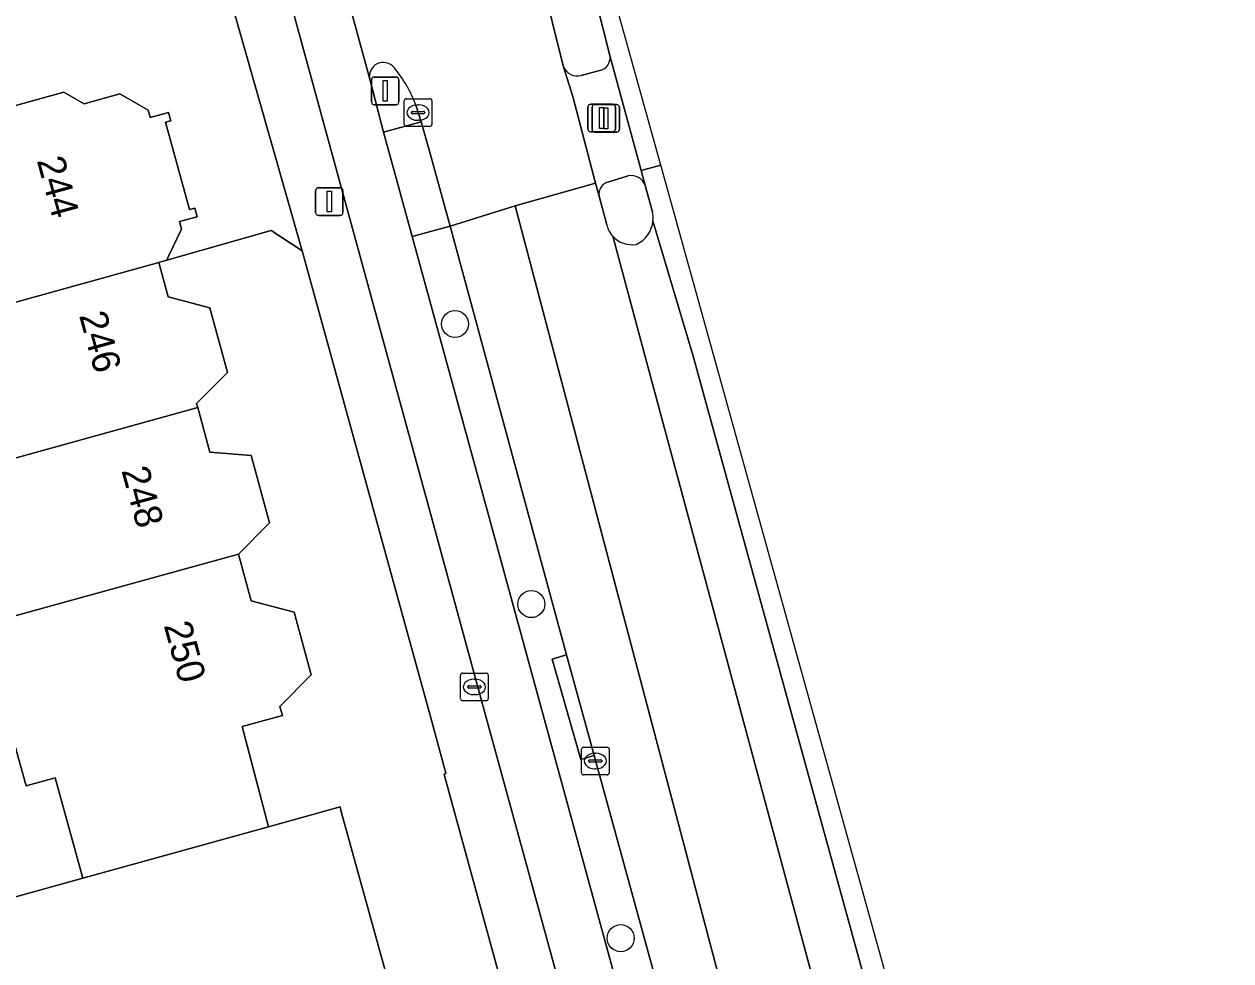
# Model space of a CAD drawing. Extents: x 162250 to 162661, y 380743 to 381606.
# Drawn here: x 162522.36 to 162566, y 381174.18 to 381208.05 of the extents above; entities that cross this region are included whole.
import ezdxf

# ---------------------------------------------------------------- set-up
doc = ezdxf.new("R2010")
doc.units = 0
for name, color, linetype in [('IMGEO_Berm_open', 7, 'Continuous'), ('IMGEO_Boom', 7, 'Continuous'), ('IMGEO_Brandkraan', 7, 'Continuous'), ('IMGEO_Erf', 7, 'Continuous'), ('IMGEO_Fietspad_gesloten', 7, 'Continuous'), ('IMGEO_Kolk', 7, 'Continuous'), ('IMGEO_Lichtmast', 7, 'Continuous'), ('IMGEO_Pand', 7, 'Continuous'), ('IMGEO_Pand_nummerreeks', 7, 'Continuous'), ('IMGEO_Rijbaan_regionaal_gesloten', 7, 'Continuous'), ('IMGEO_Verkeerseiland_open', 7, 'Continuous'), ('IMGEO_Verkeersregelinstallatiepaal', 7, 'Continuous'), ('IMGEO_Voetpad_gesloten', 7, 'Continuous'), ('IMGEO_Voetpad_open', 7, 'Continuous')]:
    doc.layers.add(name, color=color, linetype=linetype)

msp = doc.modelspace()

# ---------------------------------------------------------------- linework, layer by layer
at = {"layer": 'IMGEO_Berm_open'}
msp.add_lwpolyline([(162553.008, 381145.025), (162552.925, 381145.33), (162550.374, 381154.672), (162550.34, 381154.796), (162542.98, 381181.61), (162542.491, 381181.463), (162541.461, 381185.086), (162541.982, 381185.24), (162537.767, 381200.743), (162536.398, 381200.372), (162539.144, 381190.342), (162540.943, 381183.77), (162548.984, 381154.395), (162551.592, 381144.84), (162551.645, 381144.647), (162554.806, 381133.124), (162560.736, 381111.446), (162562.992, 381103.198), (162573.052, 381066.398), (162577.335, 381050.801)], dxfattribs=at)
at = {"layer": 'IMGEO_Boom'}
for centre in [(162537.943, 381197.208), (162540.706, 381187.08), (162543.938, 381175.003)]:
    msp.add_circle(centre, 0.489, dxfattribs=at)
at = {"layer": 'IMGEO_Brandkraan'}
for p, q in [((162538.145, 381183.661), (162538.145, 381184.513)), ((162538.22, 381184.587), (162539.072, 381184.587)), ((162539.146, 381184.513), (162539.146, 381183.661)), ((162538.404, 381184.081), (162538.404, 381184.093)), ((162538.447, 381184.13), (162538.845, 381184.13)), ((162538.633, 381184.367), (162538.658, 381184.367)), ((162538.888, 381184.093), (162538.888, 381184.081)), ((162538.842, 381184.044), (162538.444, 381184.044)), ((162538.656, 381183.807), (162538.631, 381183.807)), ((162539.072, 381183.587), (162538.22, 381183.587))]:
    msp.add_line(p, q, dxfattribs=at)
for points in [[(162538.145, 381183.661), (162538.145, 381184.513)], [(162538.22, 381184.587), (162539.072, 381184.587)], [(162539.146, 381184.513), (162539.146, 381183.661)], [(162539.072, 381183.587), (162538.22, 381183.587)]]:
    msp.add_lwpolyline(points, dxfattribs=at)
for centre, radius, start, end in [((162538.222, 381184.511), 0.0765, 91.552, 178.448), ((162538.222, 381184.511), 0.0765, 91.552, 178.448), ((162539.07, 381184.511), 0.0765, 1.552, 88.448), ((162539.07, 381184.511), 0.0765, 1.552, 88.448), ((162538.444, 381184.09), 0.0403, 85.8775, 175.7526), ((162538.441, 381184.08), 0.0366, 178.938, 274.7102), ((162538.845, 381184.087), 0.043, 264.8664, 352.4533), ((162538.849, 381184.092), 0.0386, 1.7309, 96.639), ((162538.222, 381183.663), 0.0765, 181.552, 268.448), ((162538.222, 381183.663), 0.0765, 181.552, 268.448), ((162539.07, 381183.663), 0.0765, 271.552, 358.448), ((162539.07, 381183.663), 0.0765, 271.552, 358.448)]:
    msp.add_arc(centre, radius, start, end, dxfattribs=at)
for centre, major_axis, ratio, start_param, end_param in [((162538.632, 381184.087), (-0.387, 0.002), 0.722429, 4.712389, 7.853982), ((162538.657, 381184.087), (-0.39, 0.002), 0.717154, 1.570796, 4.712389)]:
    msp.add_ellipse(centre, major_axis=major_axis, ratio=ratio, start_param=start_param, end_param=end_param, dxfattribs=at)
at = {"layer": 'IMGEO_Erf'}
for points in [[(162545.286, 381152.678), (162537.55, 381180.925), (162537.616, 381180.963), (162537.065, 381182.965), (162532.417, 381199.851), (162531.293, 381200.584), (162527.522, 381199.515), (162527.229, 381199.434), (162527.572, 381198.183), (162529.078, 381197.789), (162529.717, 381195.458), (162528.601, 381194.329), (162528.64, 381194.185), (162529.082, 381192.577), (162530.57, 381192.447), (162531.235, 381190.019), (162530.114, 381188.885), (162530.577, 381187.195), (162532.125, 381186.79), (162532.748, 381184.52), (162531.613, 381183.372), (162531.701, 381183.051), (162530.245, 381182.652), (162531.203, 381179.03), (162533.786, 381179.745), (162533.844, 381179.534), (162540.468, 381155.608)], [(162517.179, 381175.147), (162524.487, 381177.17), (162523.483, 381180.798), (162522.431, 381180.51), (162521.694, 381183.198)]]:
    msp.add_lwpolyline(points, dxfattribs=at)
at = {"layer": 'IMGEO_Fietspad_gesloten'}
for points in [[(162508.721, 381294.058), (162520.721, 381250), (162524.95, 381234.475), (162526.439, 381228.987), (162532.158, 381208.274), (162537.019, 381190.487), (162538.98, 381183.33), (162547.107, 381153.663), (162547.143, 381153.533), (162549.695, 381144.216), (162549.852, 381143.643), (162552.836, 381132.744), (162558.72, 381111.249), (162561.27, 381101.934), (162571.085, 381066.091), (162575.392, 381050.363), (162582.804, 381023.355), (162585.413, 381013.87), (162586.64, 381009.407), (162588.336, 381003.241), (162600.985, 380956.955), (162611.456, 380918.623), (162619.54, 380889.111), (162626.231, 380864.638)], [(162611.747, 380924.889), (162608.338, 380937.386), (162606.977, 380942.372), (162603.154, 380956.316), (162590.219, 381003.716), (162588.433, 381010.254), (162587.309, 381014.367), (162584.526, 381024.553), (162577.335, 381050.801), (162573.052, 381066.398), (162562.992, 381103.198), (162560.736, 381111.446), (162554.806, 381133.124), (162551.645, 381144.647), (162551.592, 381144.84), (162548.984, 381154.395), (162540.943, 381183.77), (162539.144, 381190.342), (162536.398, 381200.372), (162535.609, 381203.223), (162535.353, 381204.147), (162534.863, 381206.056), (162528.007, 381231.163)]]:
    msp.add_lwpolyline(points, dxfattribs=at)
at = {"layer": 'IMGEO_Kolk'}
for p, q in [((162536.108, 381204.425), (162536.108, 381205.277)), ((162536.183, 381205.351), (162537.035, 381205.351)), ((162536.596, 381205.131), (162536.621, 381205.131)), ((162537.109, 381205.277), (162537.109, 381204.425)), ((162536.367, 381204.845), (162536.367, 381204.857)), ((162536.805, 381204.808), (162536.407, 381204.808)), ((162536.41, 381204.894), (162536.808, 381204.894)), ((162536.851, 381204.857), (162536.851, 381204.845)), ((162537.035, 381204.351), (162536.183, 381204.351)), ((162536.619, 381204.571), (162536.594, 381204.571)), ((162542.594, 381181.905), (162543.446, 381181.905)), ((162542.519, 381180.979), (162542.519, 381181.831)), ((162543.007, 381181.685), (162543.032, 381181.685)), ((162543.52, 381181.831), (162543.52, 381180.979)), ((162542.778, 381181.399), (162542.778, 381181.411)), ((162543.216, 381181.362), (162542.818, 381181.362)), ((162542.821, 381181.448), (162543.219, 381181.448)), ((162543.03, 381181.125), (162543.005, 381181.125)), ((162543.262, 381181.411), (162543.262, 381181.399)), ((162543.446, 381180.905), (162542.594, 381180.905))]:
    msp.add_line(p, q, dxfattribs=at)
for points in [[(162536.108, 381204.425), (162536.108, 381205.277)], [(162536.183, 381205.351), (162537.035, 381205.351)], [(162537.109, 381205.277), (162537.109, 381204.425)], [(162537.035, 381204.351), (162536.183, 381204.351)], [(162542.594, 381181.905), (162543.446, 381181.905)], [(162542.519, 381180.979), (162542.519, 381181.831)], [(162543.52, 381181.831), (162543.52, 381180.979)], [(162543.446, 381180.905), (162542.594, 381180.905)]]:
    msp.add_lwpolyline(points, dxfattribs=at)
for centre, radius, start, end in [((162536.185, 381205.275), 0.0765, 91.552, 178.448), ((162536.185, 381205.275), 0.0765, 91.552, 178.448), ((162537.033, 381205.275), 0.0765, 1.552, 88.448), ((162537.033, 381205.275), 0.0765, 1.552, 88.448), ((162536.407, 381204.854), 0.0403, 85.8775, 175.7526), ((162536.404, 381204.844), 0.0366, 178.938, 274.7102), ((162536.808, 381204.851), 0.043, 264.8664, 352.4533), ((162536.812, 381204.856), 0.0386, 1.7309, 96.639), ((162536.185, 381204.427), 0.0765, 181.552, 268.448), ((162536.185, 381204.427), 0.0765, 181.552, 268.448), ((162537.033, 381204.427), 0.0765, 271.552, 358.448), ((162537.033, 381204.427), 0.0765, 271.552, 358.448), ((162542.596, 381181.829), 0.0765, 91.552, 178.448), ((162542.596, 381181.829), 0.0765, 91.552, 178.448), ((162543.444, 381181.829), 0.0765, 1.552, 88.448), ((162543.444, 381181.829), 0.0765, 1.552, 88.448), ((162542.818, 381181.408), 0.0403, 85.8775, 175.7526), ((162542.815, 381181.398), 0.0366, 178.938, 274.7102), ((162543.219, 381181.405), 0.043, 264.8664, 352.4533), ((162543.223, 381181.41), 0.0386, 1.7309, 96.639), ((162542.596, 381180.981), 0.0765, 181.552, 268.448), ((162542.596, 381180.981), 0.0765, 181.552, 268.448), ((162543.444, 381180.981), 0.0765, 271.552, 358.448), ((162543.444, 381180.981), 0.0765, 271.552, 358.448)]:
    msp.add_arc(centre, radius, start, end, dxfattribs=at)
for centre, major_axis, ratio, start_param, end_param in [((162536.595, 381204.851), (-0.387, 0.002), 0.722429, 4.712389, 7.853982), ((162536.62, 381204.851), (-0.39, 0.002), 0.717154, 1.570796, 4.712389), ((162543.006, 381181.405), (-0.387, 0.002), 0.722429, 4.712389, 7.853982), ((162543.031, 381181.405), (-0.39, 0.002), 0.717154, 1.570796, 4.712389)]:
    msp.add_ellipse(centre, major_axis=major_axis, ratio=ratio, start_param=start_param, end_param=end_param, dxfattribs=at)
at = {"layer": 'IMGEO_Lichtmast'}
for p, q in [((162542.902, 381204.241), (162542.902, 381205.041)), ((162542.902, 381205.041), (162542.902, 381204.241)), ((162543.002, 381205.141), (162543.792, 381205.141)), ((162543.792, 381205.141), (162543.002, 381205.141)), ((162543.892, 381205.041), (162543.892, 381204.241)), ((162543.892, 381204.241), (162543.892, 381205.041)), ((162543.792, 381204.141), (162543.002, 381204.141)), ((162543.002, 381204.141), (162543.792, 381204.141))]:
    msp.add_line(p, q, dxfattribs=at)
msp.add_lwpolyline([(162543.322, 381205.016), (162543.472, 381205.016), (162543.472, 381204.266), (162543.322, 381204.266), (162543.322, 381205.016)], dxfattribs=at)
for centre, start, end in [((162543.002, 381205.041), 90, 180), ((162543.002, 381205.041), 90, 180), ((162543.792, 381205.041), 0, 90), ((162543.792, 381205.041), 360, 90), ((162543.002, 381204.241), 180, 270), ((162543.002, 381204.241), 180, 270), ((162543.792, 381204.241), 270, 0), ((162543.792, 381204.241), 270, 0)]:
    msp.add_arc(centre, 0.1, start, end, dxfattribs=at)
at = {"layer": 'IMGEO_Pand'}
msp.add_lwpolyline([(162516.659, 381196.507), (162527.229, 381199.434), (162527.522, 381199.515), (162527.599, 381199.678), (162528.053, 381200.637), (162527.979, 381200.908), (162528.62, 381201.084), (162528.535, 381201.394), (162528.345, 381201.342), (162527.48, 381204.498), (162527.67, 381204.55), (162527.587, 381204.851), (162526.922, 381204.668), (162526.848, 381204.936), (162525.818, 381205.523), (162524.534, 381205.171), (162523.801, 381205.589), (162520.567, 381204.702)], dxfattribs=at)
for points in [[(162528.64, 381194.185), (162528.601, 381194.329), (162529.717, 381195.458), (162529.078, 381197.789), (162527.572, 381198.183), (162527.229, 381199.434), (162516.659, 381196.507), (162517.358, 381193.957), (162518.539, 381194.281), (162519.226, 381191.778), (162518.061, 381191.459), (162518.113, 381191.271)], [(162528.64, 381194.185), (162518.113, 381191.271), (162518.908, 381188.369), (162520.056, 381188.684), (162520.712, 381186.292), (162530.114, 381188.885), (162531.235, 381190.019), (162530.57, 381192.447), (162529.082, 381192.577)], [(162520.712, 381186.292), (162519.589, 381185.985), (162520.446, 381182.856), (162521.694, 381183.198), (162522.431, 381180.51), (162523.483, 381180.798), (162524.487, 381177.17), (162531.203, 381179.03), (162530.245, 381182.652), (162531.701, 381183.051), (162531.613, 381183.372), (162532.748, 381184.52), (162532.125, 381186.79), (162530.577, 381187.195), (162530.114, 381188.885)], [(162524.487, 381177.17), (162517.179, 381175.147), (162516.879, 381176.23), (162511.537, 381174.751), (162515.452, 381155.029), (162516.426, 381150.124), (162516.634, 381150.165), (162523.606, 381151.549), (162523.763, 381150.983), (162532.204, 381153.32), (162540.468, 381155.608), (162533.844, 381179.534), (162533.786, 381179.745), (162531.203, 381179.03)]]:
    msp.add_lwpolyline(points, close=True, dxfattribs=at)
at = {"layer": 'IMGEO_Rijbaan_regionaal_gesloten'}
for points in [[(162545.39, 381202.947), (162541.62, 381216.506), (162529.09, 381267.097), (162526.533, 381277.419), (162506.293, 381346.192), (162501.803, 381357.869), (162495.049, 381375.437), (162487.336, 381390.854), (162486.734, 381390.552), (162488.723, 381386.618), (162489.098, 381385.884)], [(162528.007, 381231.163), (162534.863, 381206.056)], [(162543.035, 381208.92), (162543.558, 381206.865), (162544.673, 381202.753), (162545.39, 381202.947)], [(162536.536, 381205.084), (162536.726, 381204.513), (162537.019, 381203.451), (162537.767, 381200.743), (162540.124, 381201.475), (162543.029, 381202.295), (162542.209, 381205.429), (162541.867, 381206.505), (162541.523, 381207.891), (162541.384, 381208.45)], [(162604.23, 380992.009), (162599.016, 381010.476), (162591.435, 381037.32), (162559.589, 381151.874), (162545.39, 381202.947), (162544.673, 381202.753), (162544.818, 381202.219), (162545.081, 381201.258)], [(162543.432, 381200.793), (162543.152, 381201.827), (162543.029, 381202.295), (162540.124, 381201.475), (162556.025, 381141.32), (162556.267, 381140.725), (162561.982, 381119.806), (162563.768, 381113.225), (162565.639, 381106.468), (162577.173, 381064.266), (162584.449, 381036.623), (162587.606, 381025.501), (162590.528, 381015.212), (162591.173, 381012.938), (162595.042, 380999.313), (162597.541, 380990.23), (162600.546, 380991.029), (162599.675, 380994.301)], [(162540.124, 381201.475), (162537.767, 381200.743), (162541.982, 381185.24), (162542.98, 381181.61), (162550.34, 381154.796), (162550.374, 381154.672), (162552.925, 381145.33), (162553.008, 381145.025)], [(162555.673, 381142.187), (162556.025, 381141.32), (162540.124, 381201.475)], [(162569.845, 381112.873), (162562.469, 381138.221), (162546.555, 381196.038), (162545.104, 381200.933)], [(162545.104, 381200.933), (162546.555, 381196.038), (162562.469, 381138.221), (162569.845, 381112.873)], [(162543.648, 381200.38), (162544.792, 381196.117), (162567.409, 381112.237)], [(162567.409, 381112.237), (162544.792, 381196.117), (162543.648, 381200.38)]]:
    msp.add_lwpolyline(points, dxfattribs=at)
for centre, radius, start, end in [((162535.35, 381206.164), 0.499, 38.7418, 192.4891), ((162532.527, 381203.713), 4.237, 18.8833, 40.704), ((162544.046, 381201.021), 1.062, 355.2201, 12.8759), ((162544.348, 381201.009), 0.942, 193.2792, 221.9401), ((162544.08, 381201.024), 1.028, 294.0476, 354.941), ((162544.343, 381201.01), 0.938, 222.2051, 279.557)]:
    msp.add_arc(centre, radius, start, end, dxfattribs=at)
at = {"layer": 'IMGEO_Verkeerseiland_open'}
for points in [[(162543.558, 381206.865), (162543.035, 381208.92)], [(162541.384, 381208.45), (162541.523, 381207.891), (162541.867, 381206.505)], [(162542.509, 381206.19), (162543.219, 381206.38)], [(162534.863, 381206.056), (162535.353, 381204.147), (162536.726, 381204.513), (162536.536, 381205.084)], [(162544.21, 381202.56), (162543.475, 381202.337)], [(162545.081, 381201.258), (162544.818, 381202.219)], [(162543.152, 381201.827), (162543.432, 381200.793)]]:
    msp.add_lwpolyline(points, dxfattribs=at)
for centre, radius, start, end in [((162543.067, 381206.847), 0.491, 287.9873, 2.108), ((162535.35, 381206.164), 0.499, 38.7418, 192.4891), ((162532.527, 381203.713), 4.237, 18.8833, 40.704), ((162542.372, 381206.723), 0.55, 203.3585, 284.3714), ((162544.322, 381202.048), 0.525, 19.0758, 102.352), ((162543.598, 381201.902), 0.452, 105.7592, 189.5459), ((162544.046, 381201.021), 1.062, 355.2201, 12.8759), ((162544.348, 381201.009), 0.942, 193.2792, 221.9401), ((162544.08, 381201.024), 1.028, 294.0476, 354.941), ((162544.343, 381201.01), 0.938, 222.2051, 279.557)]:
    msp.add_arc(centre, radius, start, end, dxfattribs=at)
at = {"layer": 'IMGEO_Verkeersregelinstallatiepaal'}
for p, q in [((162534.924, 381205.235), (162534.924, 381206.035)), ((162534.924, 381206.035), (162534.924, 381205.235)), ((162535.024, 381206.135), (162535.814, 381206.135)), ((162535.814, 381206.135), (162535.024, 381206.135)), ((162535.914, 381206.035), (162535.914, 381205.235)), ((162535.914, 381205.235), (162535.914, 381206.035)), ((162535.814, 381205.135), (162535.024, 381205.135)), ((162535.024, 381205.135), (162535.814, 381205.135)), ((162542.754, 381204.255), (162542.754, 381205.055)), ((162542.754, 381205.055), (162542.754, 381204.255)), ((162542.854, 381205.155), (162543.644, 381205.155)), ((162543.644, 381205.155), (162542.854, 381205.155)), ((162543.744, 381205.055), (162543.744, 381204.255)), ((162543.744, 381204.255), (162543.744, 381205.055)), ((162543.644, 381204.155), (162542.854, 381204.155)), ((162542.854, 381204.155), (162543.644, 381204.155)), ((162532.904, 381201.232), (162532.904, 381202.032)), ((162532.904, 381202.032), (162532.904, 381201.232)), ((162533.004, 381202.132), (162533.794, 381202.132)), ((162533.794, 381202.132), (162533.004, 381202.132)), ((162533.894, 381202.032), (162533.894, 381201.232)), ((162533.894, 381201.232), (162533.894, 381202.032)), ((162533.794, 381201.132), (162533.004, 381201.132)), ((162533.004, 381201.132), (162533.794, 381201.132))]:
    msp.add_line(p, q, dxfattribs=at)
for points in [[(162535.344, 381206.01), (162535.494, 381206.01), (162535.494, 381205.26), (162535.344, 381205.26), (162535.344, 381206.01)], [(162543.174, 381205.03), (162543.324, 381205.03), (162543.324, 381204.28), (162543.174, 381204.28), (162543.174, 381205.03)], [(162533.324, 381202.007), (162533.474, 381202.007), (162533.474, 381201.257), (162533.324, 381201.257), (162533.324, 381202.007)]]:
    msp.add_lwpolyline(points, dxfattribs=at)
for centre, start, end in [((162535.024, 381206.035), 90, 180), ((162535.024, 381206.035), 90, 180), ((162535.814, 381206.035), 0, 90), ((162535.814, 381206.035), 360, 90), ((162535.024, 381205.235), 180, 270), ((162535.024, 381205.235), 180, 270), ((162535.814, 381205.235), 270, 0), ((162535.814, 381205.235), 270, 0), ((162542.854, 381205.055), 90, 180), ((162542.854, 381205.055), 90, 180), ((162543.644, 381205.055), 0, 90), ((162543.644, 381205.055), 360, 90), ((162542.854, 381204.255), 180, 270), ((162542.854, 381204.255), 180, 270), ((162543.644, 381204.255), 270, 0), ((162543.644, 381204.255), 270, 0), ((162533.004, 381202.032), 90, 180), ((162533.004, 381202.032), 90, 180), ((162533.794, 381202.032), 0, 90), ((162533.794, 381202.032), 360, 90), ((162533.004, 381201.232), 180, 270), ((162533.004, 381201.232), 180, 270), ((162533.794, 381201.232), 270, 0), ((162533.794, 381201.232), 270, 0)]:
    msp.add_arc(centre, 0.1, start, end, dxfattribs=at)
at = {"layer": 'IMGEO_Voetpad_gesloten'}
for points in [[(162544.818, 381202.219), (162544.673, 381202.753), (162543.558, 381206.865)], [(162541.867, 381206.505), (162542.209, 381205.429), (162543.029, 381202.295), (162543.152, 381201.827)], [(162543.219, 381206.38), (162542.509, 381206.19)], [(162543.475, 381202.337), (162544.21, 381202.56)]]:
    msp.add_lwpolyline(points, dxfattribs=at)
for centre, radius, start, end in [((162543.067, 381206.847), 0.491, 287.9873, 2.108), ((162542.372, 381206.723), 0.55, 203.3585, 284.3714), ((162544.322, 381202.048), 0.525, 19.0758, 102.352), ((162543.598, 381201.902), 0.452, 105.7592, 189.5459)]:
    msp.add_arc(centre, radius, start, end, dxfattribs=at)
at = {"layer": 'IMGEO_Voetpad_open'}
for points in [[(162520.567, 381204.702), (162523.801, 381205.589), (162524.534, 381205.171), (162525.818, 381205.523), (162526.848, 381204.936), (162526.922, 381204.668), (162527.587, 381204.851), (162527.67, 381204.55), (162527.48, 381204.498), (162528.345, 381201.342), (162528.535, 381201.394), (162528.62, 381201.084), (162527.979, 381200.908), (162528.053, 381200.637), (162527.599, 381199.678), (162527.522, 381199.515), (162531.293, 381200.584), (162532.417, 381199.851), (162530.224, 381207.557), (162529.072, 381211.608)], [(162529.072, 381211.608), (162530.224, 381207.557), (162532.417, 381199.851), (162537.065, 381182.965), (162537.616, 381180.963), (162537.55, 381180.925), (162545.286, 381152.678), (162547.143, 381153.533), (162547.107, 381153.663), (162538.98, 381183.33), (162537.019, 381190.487), (162532.158, 381208.274)]]:
    msp.add_lwpolyline(points, dxfattribs=at)
for points in [[(162536.398, 381200.372), (162537.767, 381200.743), (162537.019, 381203.451), (162536.726, 381204.513), (162535.353, 381204.147), (162535.609, 381203.223)], [(162541.982, 381185.24), (162541.461, 381185.086), (162542.491, 381181.463), (162542.98, 381181.61)]]:
    msp.add_lwpolyline(points, close=True, dxfattribs=at)

# ---------------------------------------------------------------- texts
at = {"layer": 'IMGEO_Pand_nummerreeks'}
for s, p in [('244', (162522.816, 381203.121)), ('246', (162524.346, 381197.519)), ('248', (162525.877, 381191.915)), ('250', (162527.408, 381186.313))]:
    msp.add_text(s, height=1, rotation=285.2853, dxfattribs=at).set_placement(p)

doc.saveas('drawing.dxf')
